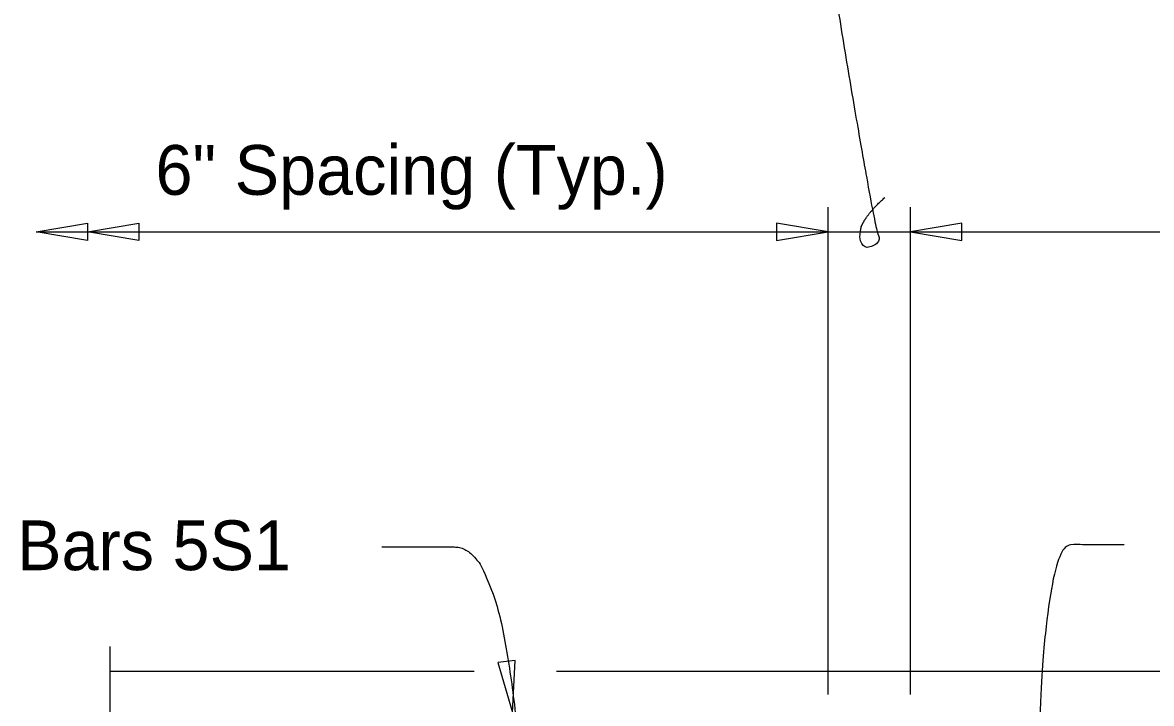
# Model space of a CAD drawing. Extents: x 120588.1 to 120659.6, y 120683.4 to 120715.5.
# Drawn here: x 120588.166 to 120592.737, y 120704.29 to 120707.048 of the extents above; entities that cross this region are included whole.
import ezdxf

# ---------------------------------------------------------------- set-up
doc = ezdxf.new("R2010")
doc.units = 0
for name, color, linetype in [('Patterning', 7, 'Continuous'), ('SheetBorder_dp', 7, 'Continuous'), ('SheetLines_dp', 7, 'Continuous')]:
    doc.layers.add(name, color=color, linetype=linetype)

msp = doc.modelspace()

# ---------------------------------------------------------------- linework, layer by layer
at = {"layer": 'SheetBorder_dp'}
for p, q in [((120588.5208, 120704.4203), (120589.9943, 120704.4203)), ((120590.328, 120704.4203), (120597.939, 120704.4203))]:
    msp.add_line(p, q, dxfattribs=at)
at = {"layer": 'SheetLines_dp'}
for p, q in [((120591.4273, 120704.3267), (120591.4273, 120706.3004)), ((120591.7607, 120704.3267), (120591.7607, 120706.3004)), ((120588.2204, 120706.2005), (120604.4273, 120706.2005))]:
    msp.add_line(p, q, dxfattribs=at)
for points in [[(120588.2204, 120706.2005), (120588.4287, 120706.2357), (120588.4287, 120706.1652)], [(120588.4287, 120706.2005), (120588.6369, 120706.2357), (120588.6369, 120706.1652)], [(120591.4273, 120706.2005), (120591.219, 120706.2358), (120591.219, 120706.1652)], [(120591.7607, 120706.2005), (120591.9689, 120706.1652), (120591.9689, 120706.2358)], [(120590.1489, 120704.2537), (120590.1602, 120704.4646), (120590.0901, 120704.4566)]]:
    msp.add_lwpolyline(points, close=True, dxfattribs=at)
msp.add_lwpolyline([(120588.5208, 120699.087), (120588.5208, 120701.3501), (120588.4174, 120701.3501), (120588.5208, 120701.3951), (120588.6241, 120701.4401), (120588.5208, 120701.4401), (120588.5208, 120704.5204)], dxfattribs=at)
for points in [[(120591.9365, 120708.5758), (120591.3261, 120708.6641), (120591.3859, 120707.5835), (120591.6142, 120706.2216), (120591.6459, 120706.1593), (120591.5624, 120706.1242), (120591.5493, 120706.2425), (120591.6569, 120706.3395)], [(120589.6208, 120704.924), (120589.7816, 120704.924), (120590.0497, 120704.924), (120590.1927, 120704.131), (120590.1927, 120703.1294), (120590.1927, 120699.2537)], [(120592.6255, 120704.9329), (120592.4825, 120704.9329), (120592.3336, 120704.9329), (120592.2561, 120703.9432), (120592.2563, 120699.7537)]]:
    msp.add_open_spline(points, degree=2, dxfattribs=at)

# ---------------------------------------------------------------- texts
at = {"layer": 'Patterning'}
for s, p in [('6" Spacing (Typ.)', (120588.7039, 120706.3505)), ('Bars 5S1', (120588.1436, 120704.83))]:
    msp.add_text(s, height=0.2016, dxfattribs=at).set_placement(p)

doc.saveas('drawing.dxf')
